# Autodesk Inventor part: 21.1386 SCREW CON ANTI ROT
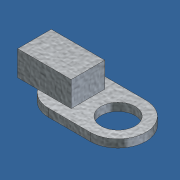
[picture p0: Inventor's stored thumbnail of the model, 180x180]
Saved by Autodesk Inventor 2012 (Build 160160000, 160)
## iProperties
Created: 2006-12
Part Number: 21.1386 SCREW CON ANTI ROT
Document SubType Name: Modeling
Designer: Andy Moles
Material: Aluminum-6061
Mass: 2.84475 g
Surface Area: 9.25543 cm^2
Volume: 1.04972 cm^3
Density: 2.71 g/cm^3
Author: Andy Moles
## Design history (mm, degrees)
sketch "Sketch1"
  geometry: L1 (-19.518, 6.726)-(-9.535, 6.726); L2 (-19.518, -6.66)-(-9.535, -6.66); C1 r 4.1 at (-9.535, 0.033); A1 r 6.693 centre (-9.535, 0.033) between (-9.535, -6.66) and (-9.535, 6.726); A2 r 6.693 centre (-19.518, 0.033) between (-19.518, 6.726) and (-19.518, -6.66)
  constraints: 4 end point, 4 point on circle, 3 centre point, 2 tangent, 1 coincident, 1 horizontal, 1 horizontal alignment, 1 parallel
  dimensions: "d0" = 8.2 diameter of C1; "d1" = 13.3858 diameter of A1; "d2" = 13.3858 diameter of A2 (= d1); "d3" = 23.368 dimension on A1 A2
extrude "Extrusion1" new body sketch "Sketch1" distance "d4" = 1.9; taper "d5" = 0 deg
sketch "Sketch2"
  geometry: L1 (-16.76, 4.071)-(-29.637, 4.071); L2 (-29.637, 4.071)-(-29.637, -4.006); L3 (-29.637, -4.006)-(-16.76, -4.006); L4 (-16.76, -4.006)-(-16.76, 4.071); L5 (-16.76, -4.006)-(-29.637, 4.071); C1 r 4.1 at (-9.535, 0.033) reference; A1 r 6.693 centre (-19.518, 0.033) between (-19.518, 6.726) and (-19.518, -6.66) reference; 2 further points
  constraints: 10 end point, 2 parallel, 1 horizontal, 1 horizontal alignment, 1 midpoint, 1 perpendicular
  dimensions: "d6" = 12.8778 distance of L1.start L1.end; "d7" = 8.0772 distance of L1.end L2.end; "d8" = 16.002 distance edge to line of C1 L2
extrude "Extrusion2" join sketch "Sketch2" distance "d9" = 6.0452; taper "d10" = 0 deg
body "Solid1"
